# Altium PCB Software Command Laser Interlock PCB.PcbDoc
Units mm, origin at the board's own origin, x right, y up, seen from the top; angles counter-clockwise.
Board outline 50 x 70 mm, 2 copper layers (Top Layer, Bottom Layer); 14 components, 12 nets, 69 pads, 8 vias.
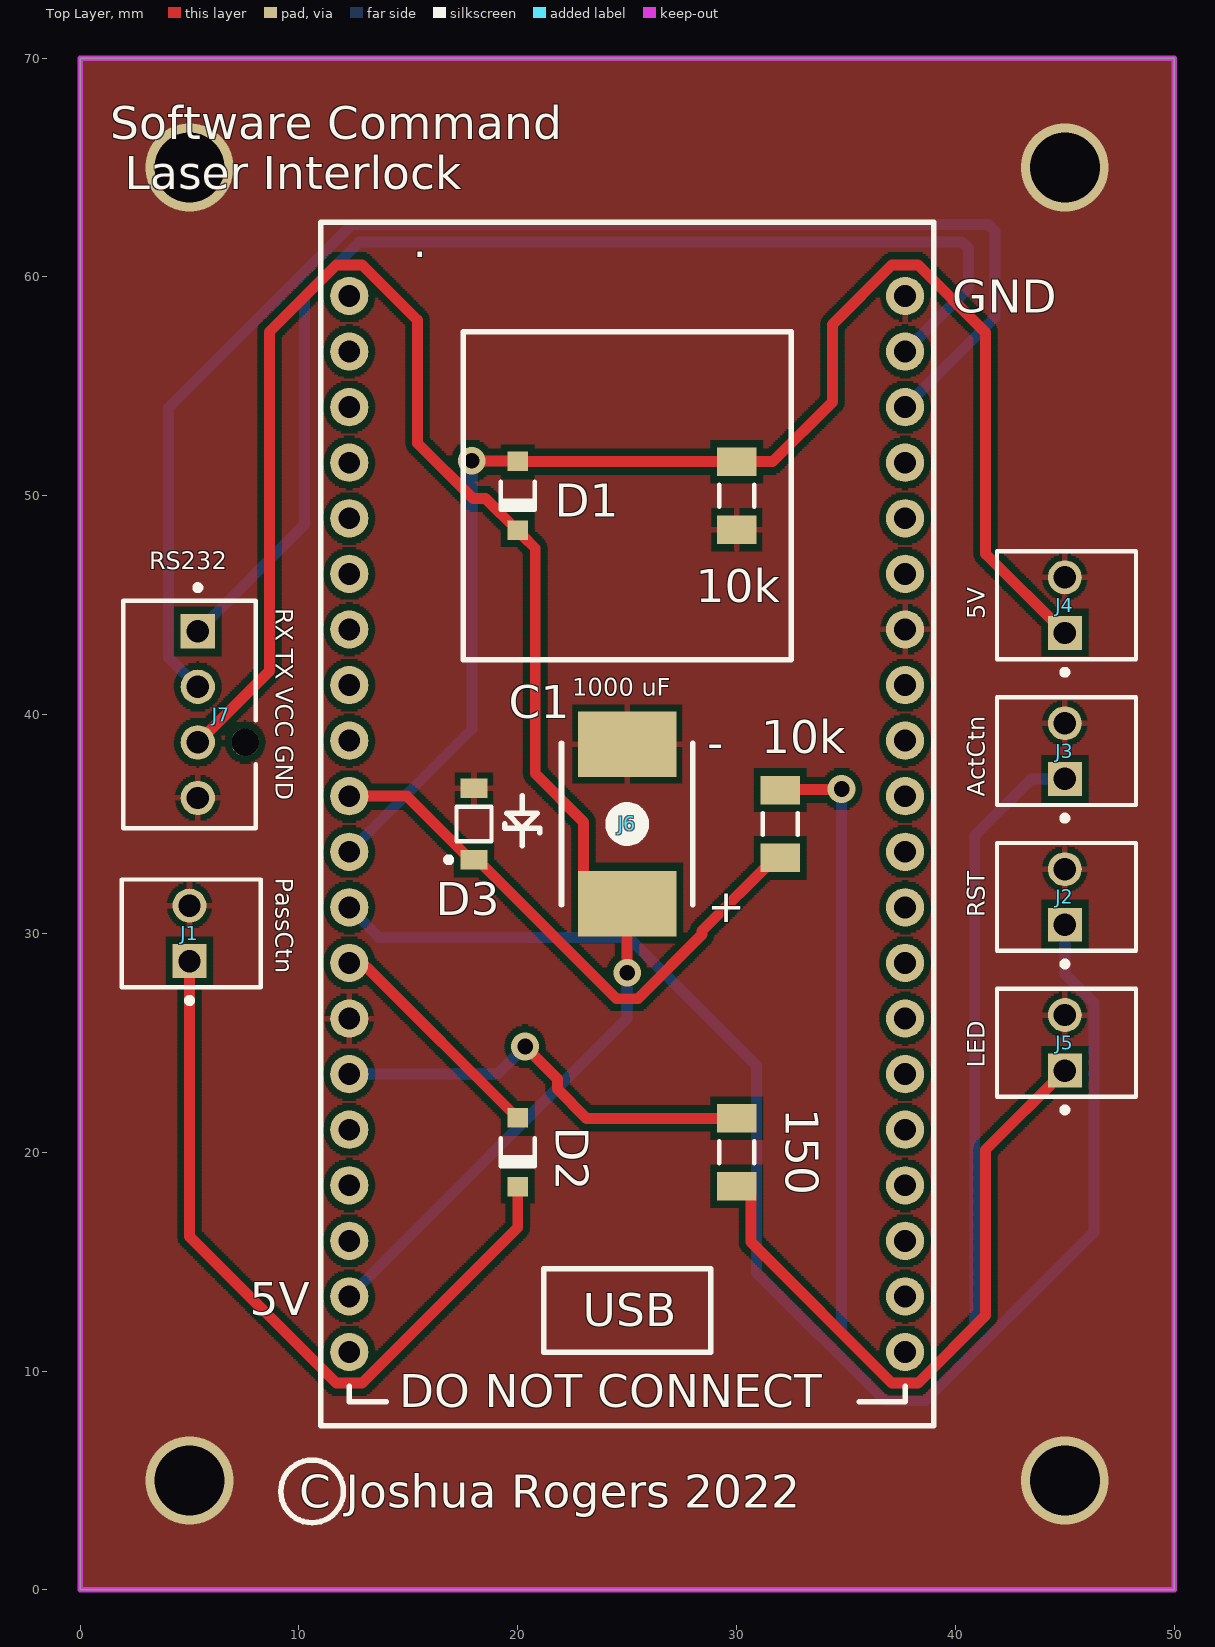
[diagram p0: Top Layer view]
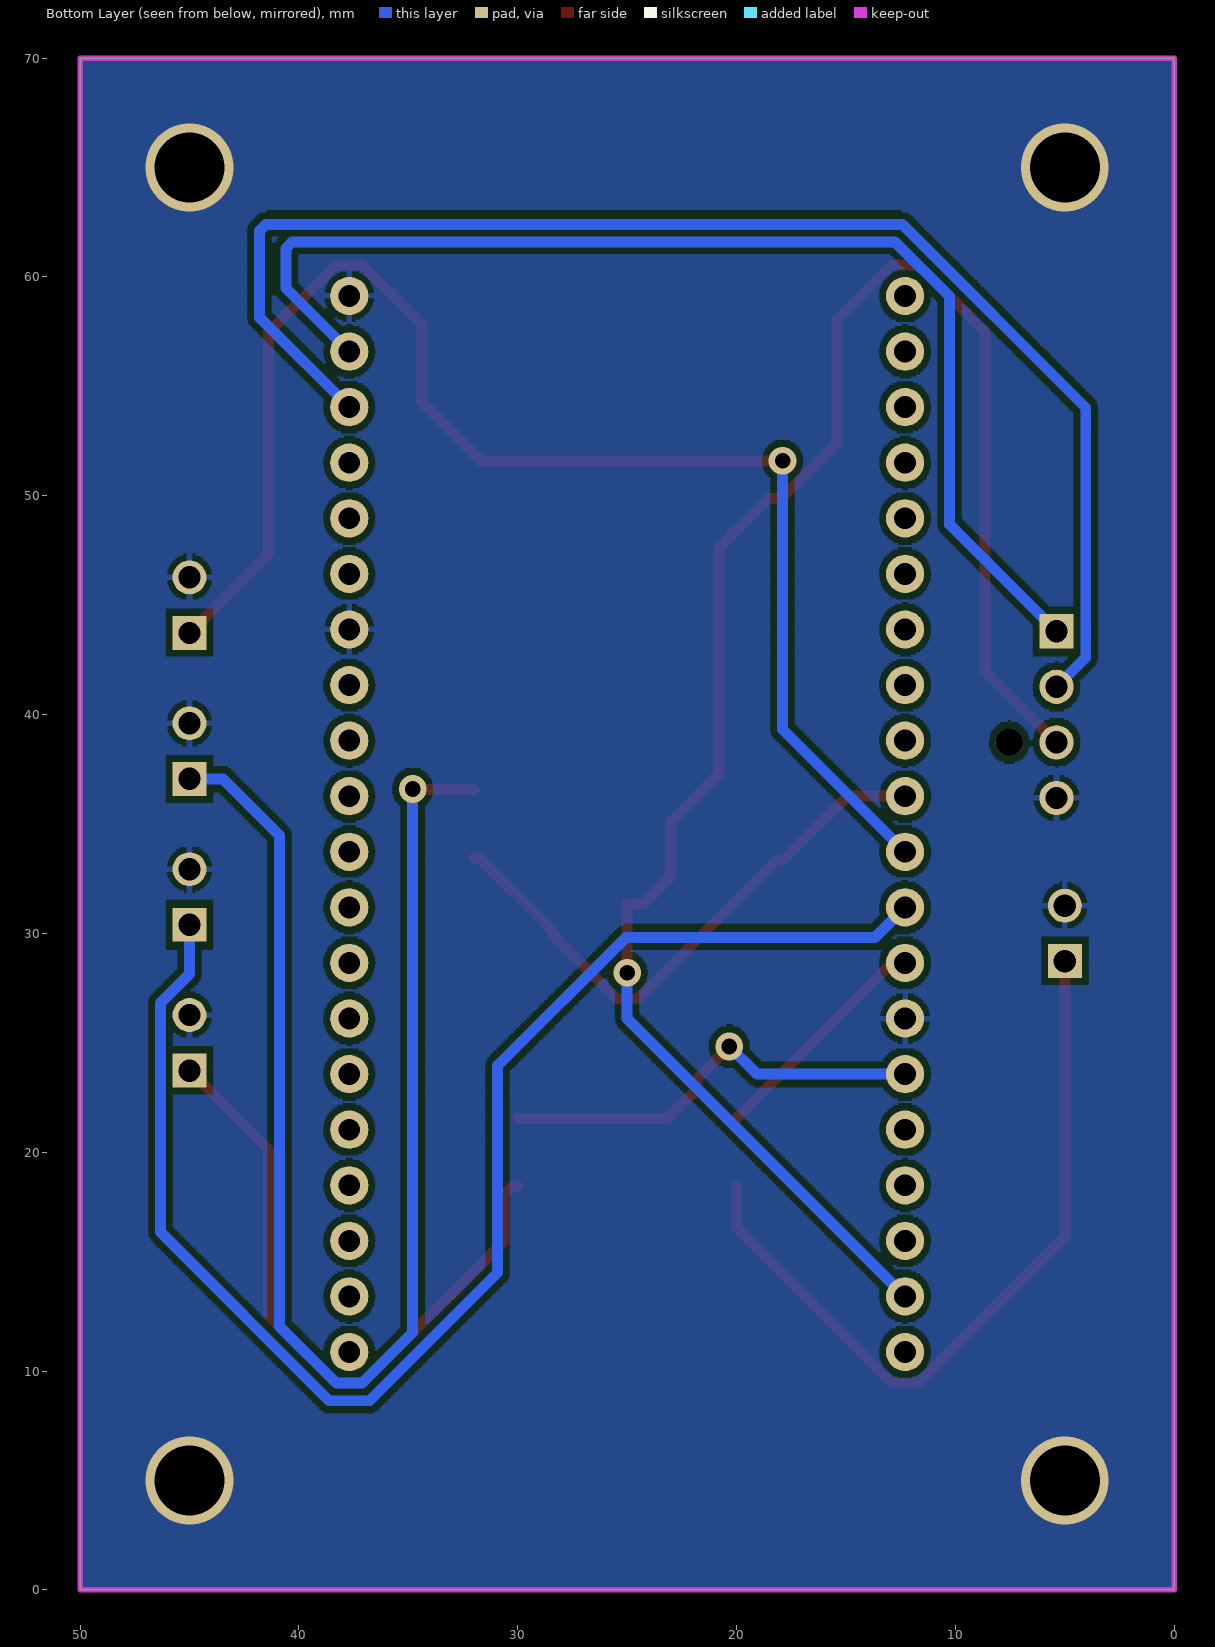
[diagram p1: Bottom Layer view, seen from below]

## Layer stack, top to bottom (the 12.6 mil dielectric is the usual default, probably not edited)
Top Solder: solder mask 0.0102, Solder Resist, Dk 3.5
Top Layer: signal copper 0.0356
Dielectric 1: dielectric 0.32, FR-4, Dk 4.8
Bottom Layer: signal copper 0.0356
Bottom Solder: solder mask 0.0102, Solder Resist, Dk 3.5

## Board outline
0,0 0,70 50,70 50,0

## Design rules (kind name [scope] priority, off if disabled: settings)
Clearance [All] p1: gap=0.3 ignorepadtopadclearanceinfootprint=FALSE
DiffPairsRouting [All] p1: maxlimit=2 minlimit=0.3 mostfreqgap=0.5 toplayer_minwidth=0.3 toplayer_maxwidth=2 toplayer_prefwidth=0.5 bottomlayer_minwidth=0.3 bottomlayer_maxwidth=2 bottomlayer_prefwidth=0.5 maxuncoupledlength=12.7
HoleSize [All] p1: absolutevalues=TRUE maxlimit=10 minlimit=0.3 maxpercent=80.000 minpercent=20.000
HoleToHoleClearance [All] p1: gap=0.6 allowstackedmicrovias=TRUE
MinimumSolderMaskSliver [All] p1: minsoldermaskwidth=0.3
PolygonConnect [All] p1: connectstyle=Relief reliefconductorwidth=0.254 reliefentries=4 polygonreliefangle="90 Angle" airgapwidth=0.254
RoutingVias [All] p1: holewidth=0.711 width=1.27 viastyle="Through Hole" minholewidth=0.711 minwidth=1.27 maxholewidth=0.711 maxwidth=1.27
SilkToSilkClearance [All] p1: silktosilkclearance=0.3
SolderMaskExpansion [All] p1: expansion=0.102 istentingtop=FALSE
Width [All] p1: maxlimit=2 minlimit=0.3 preferedwidth=0.5
25 further rules are at their usual default settings.

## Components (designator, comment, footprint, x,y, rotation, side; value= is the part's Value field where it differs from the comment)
10k "CRCW120610K0JNEA" RESC3216X60X45ML10T20 32,35 r270 top (schematic designator R3)
10k "CRCW120610K0JNEA" RESC3216X60X45ML10T20 30,50 r90 top (schematic designator R1)
150 "CRCW1206150RFKEA" RESC3216X60X45ML10T20 30,20 r90 top (schematic designator R2)
C1 "1000 uF SMD cap" "1000 uF SMD Cap" 25,35 r0 top
D1 "1N4148W-7-F" DIOD-SOD123-2_V 20,50 r270 top
D2 "1N4148W-7-F" DIOD-SOD123-2_V 20,20 r270 top
D3 "MMSZ4688T1G" ONSC-SOD-123-2-425-04_V 18,35 r90 top
J1 "22-23-2021" MOLX-22-23-2021_V 5,30 r90 top
J2 "22-23-2021" MOLX-22-23-2021_V 45,31.667 r90 top
J3 "22-23-2021" MOLX-22-23-2021_V 45,38.333 r90 top
J4 "22-23-2021" MOLX-22-23-2021_V 45,45 r90 top
J5 "22-23-2021" MOLX-22-23-2021_V 45,25 r90 top
J6 "ESP32" "ESP32 FOOTPRINT" 25,35 r0 top
J7 "47053-1000" FP-47053-1000-MFG 5,40 r90 top

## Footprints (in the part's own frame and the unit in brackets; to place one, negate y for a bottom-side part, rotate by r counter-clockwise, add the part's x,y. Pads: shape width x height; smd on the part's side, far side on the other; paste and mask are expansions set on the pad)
"1000 uF SMD Cap" [mm]
  rect 4.5x3 smd: 1(0,3.65) 2(0,-3.65)
  silkscreen extent -3,-3.7 3,3.7
DIOD-SOD123-2_V [mm] "SOD123, 2-Leads, Body 2.7x1.55mm, Height 1.45mm"
  rect 0.9x0.95 smd: 1(-1.575,0) 2(1.575,0)
  silkscreen extent -0.64,-0.82 0.64,0.77, body extent -1.35,-0.77 1.35,0.77, height 1.45
"ESP32 FOOTPRINT" [mm]
  round 1.75 hole 1: 1(-12.7,24.13) 2(-12.7,21.59) 3(-12.7,19.05) 4(-12.7,16.51) 5(-12.7,13.97) 6(-12.7,11.43) 7(-12.7,8.89) 8(-12.7,6.35) 9(-12.7,3.81) 10(-12.7,1.27) 11(-12.7,-1.27) 12(-12.7,-3.81) 13(-12.7,-6.35) 14(-12.7,-8.89) 15(-12.7,-11.43) 16(-12.7,-13.97) 17(-12.7,-16.51) 18(-12.7,-19.05) 19(-12.7,-21.59) 20(-12.7,-24.13) 21(12.7,24.13) 22(12.7,21.59) 23(12.7,19.05) 24(12.7,16.51) 25(12.7,13.97) 26(12.7,11.43) 27(12.7,8.89) 28(12.7,6.35) 29(12.7,3.81) 30(12.7,1.27) 31(12.7,-1.27) 32(12.7,-3.81) 33(12.7,-6.35) 34(12.7,-8.89) 35(12.7,-11.43) 36(12.7,-13.97) 37(12.7,-16.51) 38(12.7,-19.05) 39(12.7,-21.59) 40(12.7,-24.13)
  silkscreen extent -14,-27.5 14,27.5
FP-47053-1000-MFG [mm]
  rect 1.57x1.57 hole 1.02 paste-1000 mask+0: 1(3.81,-0.38)
  round 1.57 hole 1.02 paste-1000 mask+0: 2(1.27,-0.38) 3(-1.27,-0.38) 4(-3.81,-0.38)
  round 1.25 hole 1.25 unplated paste-1000 mask+0: ""(-1.27,-2.54)
  silkscreen extent -5.2,-3.02 5.92,3.02, body extent -5.3,-3.26 5.3,3.12, height 0.25
MOLX-22-23-2021_V [mm] "THD, 2-Leads, Body 6.35x4.93mm, Pitch 2.54mm"
  rect 1.55x1.55 hole 1.02: 1(-1.27,0)
  round 1.55 hole 1.02: 2(1.27,0)
  silkscreen extent -3.19,-3.25 2.46,3.1, body extent -2.46,-3.25 2.46,3.1, height 10.66
ONSC-SOD-123-2-425-04_V [mm] "SOD, 2-Leads, Body 2.69x1.6mm"
  rect 0.91x1.22 smd: 1(-1.635,0) 2(1.635,0)
  silkscreen extent -1.76,-0.8 0.78,1.28, body extent -1.35,-0.8 1.35,0.8, height 1.35
RESC3216X60X45ML10T20 [mm] "Chip Resistor, 2-Leads, Body 3.20x1.60mm, IPC Low Density"
  rect 1.3x1.8 smd: 1(-1.55,0) 2(1.55,0)
  silkscreen extent -0.5,-0.8 0.5,0.8, body extent -1.65,-0.85 1.65,0.85, height 0.6

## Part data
10k 10k: library part CMP-2003-04808-1, Manufacturer="Vishay Dale"
150: library part CMP-2003-01812-1, Manufacturer="Vishay Dale"
C1: "https://uk.farnell.com/kemet/t523h108m010ape070/cap-1000-f-10v-20/dp/2913804"
D1 D2: library part CMP-2000-04932-2, "Fast Switching Diode, 100 V, 0.15 A, -65 to 150 degC, 2-Pin?SOD123, RoHS, Tape and Reel", If - Forward Current=0.15A, Ir - Reverse Current=1uA, Manufacturer=DiodesIncorporated, Max Surge Current=2A, Maximum Operating Temperature=+150C, Minimum Operating Temperature=-65C, Operating Temperature Range=-65Cto+150C, Package / Case=SOD-123, Package Reference=SOD123-2, Peak Reverse Voltage=100V, Vf - Forward Voltage=1.25V
D3: library part CMP-1060-00561-1, "Zener Voltage Regulator, 500 mW, 2-Pin SOD-123, Pb-Free, Tape and Reel", Manufacturer="On Semiconductor"
J1 J2 J3 J4 J5: library part CMP-1704-00001-3, "Male Header, Pitch 2.54 mm, 1 x 2 Position, Height 10.67 mm, Tail Length 3.56 mm, 0 to 75 degC, RoHS, Bulk", Max Operating Temperature="75 degC", Min Operating Temperature="0 degC", Package Quantity=3000
J6: "2 x 1 row x 20 position header sockets to house the ESP32 DEV board"
J7: library part CMP-04776-000290-1, "CONN HEADER VERT 4POS 2.54MM", Current Rating=4A, Housing Color=Beige, Max Operating Temperature=75°C, Min Operating Temperature=0°C, Package Quantity=12000, Voltage Rating=250V

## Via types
v1: diameter 1.27, hole 0.711, Top Layer to Bottom Layer, 4 vias
v2: diameter 4, hole 3.2, Top Layer to Bottom Layer, 4 vias

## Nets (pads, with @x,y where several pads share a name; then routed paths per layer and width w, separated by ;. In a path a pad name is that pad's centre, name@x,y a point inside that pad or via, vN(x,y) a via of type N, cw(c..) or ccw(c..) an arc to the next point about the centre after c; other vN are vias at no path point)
5VPSU: 10k.2@30,51.55 D1.1 J4.1 J6.11 | length 66
  Top Layer w0.5: v1(17.9,51.6) 17.913,51.587 19.988,51.587 D1.1 20.013,51.562 31.65,51.562 34.38,54.292 34.38,57.825 37.11,60.555 38.29,60.555 41.383,57.463 41.383,47.347 J4.1
  Bottom Layer w0.5: J6.11 17.9,39.33 v1(17.9,51.6)
ActiveCurtain: 10k.1@32,36.55 J3.1 | length 63.4
  Top Layer w0.5: 10k.1@32,36.55 32.025,36.575 34.775,36.575 v1(34.8,36.6)
  Bottom Layer w0.5: v1(34.8,36.6) 34.8,11.755 37.11,9.445 38.29,9.445 40.883,12.037 40.883,34.471 43.475,37.063 J3.1
ActiveCurtainPin: 10k.2@32,33.45 D3.1 J6.10 | length 26.3
  Top Layer w0.5: J6.10 14.94,36.27 17.845,33.365 D3.1 18.155,33.365 24.505,27.015 25.491,27.015 28.42,29.945 28.42,30.12 31.75,33.45 10k.2@32,33.45
GND: 10k.1@30,48.45 C1.1 D3.2 J1.2 J2.2 J3.2 J4.2 J5.2 J6.14 J6.21 J6.27 J7.4
  other v2: 5,5 45,5 5,65 45,65
LED: 150.1 J5.1 | length 30.3
  Top Layer w0.5: 150.1 30.25,18.45 30.65,18.05 30.65,15.905 37.11,9.445 38.29,9.445 41.383,12.537 41.383,20.113 J5.1
LEDPin: 150.2 J6.15 | length 19.9
  Top Layer w0.5: v1(20.333,24.833) 21.815,23.351 21.815,22.885 23.15,21.55 150.2
  Bottom Layer w0.5: J6.15 19.07,23.57 v1(20.333,24.833)
PassiveCurtain: D2.2 J1.1 | length 35.2
  Top Layer w0.5: J1.1 5,16.155 11.71,9.445 12.89,9.445 20,16.555 D2.2
PassiveCurtainPin: D2.1 J6.13 | length 10.6
  Top Layer w0.5: J6.13 12.539,28.411 13.139,28.411 19.975,21.575 D2.1
ResetButton: J2.1 J6.12 | length 66.7
  Bottom Layer w0.5: J6.12 13.669,29.821 25.055,29.821 30.917,23.959 30.917,14.507 36.778,8.645 38.622,8.645 46.325,16.348 46.325,26.819 45,28.144 J2.1
RX: J6.22 J7.1 | length 54.7
  Bottom Layer w0.5: J7.1 10.261,48.691 10.261,59.106 12.755,61.6 40.307,61.6 40.6,61.307 40.6,59.49 J6.22
TX: J6.23 J7.2 | length 64.4
  Bottom Layer w0.5: J7.2 4.045,42.605 4.045,54.022 12.423,62.4 41.507,62.4 41.8,62.107 41.8,58.15 J6.23
VCC: C1.2 D1.2 J6.19 J7.3 | length 83.9
  Top Layer w0.5: J7.3 8.647,41.997 8.647,57.492 11.71,60.555 12.89,60.555 15.424,58.022 15.424,52.4 17.957,49.867 18.533,49.867 19.975,48.425 D1.2 20.025,48.425 20.225,48.225 20.225,48.175 20.8,47.6 20.8,37.3 23,35.1 23,32.6 24.25,31.35 C1.2 v1(25,28.2)
  Bottom Layer w0.5: J6.19 25,26.11 v1(25,28.2)
pads on no net: J6.1 J6.2 J6.3 J6.4 J6.5 J6.6 J6.7 J6.8 J6.9 J6.16 J6.17 J6.18 J6.20 J6.24 J6.25 J6.26 J6.28 J6.29 J6.30 J6.31 J6.32 J6.33 J6.34 J6.35 J6.36 J6.37 J6.38 J6.39 J6.40 J7.

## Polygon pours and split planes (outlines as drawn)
GND on Bottom Layer "GND_L02_P001" (hatched Horizontal grid 0.1 track 0.1, pour order 1): 0,0 50,0 50,70 0,70
GND on Top Layer "GND_L01_P000" (hatched Horizontal grid 0.1 track 0.1, pour order 0): 0,0 50,0 50,70 0,70

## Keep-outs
Keep-Out Layer:
  the board outline again, w0.254

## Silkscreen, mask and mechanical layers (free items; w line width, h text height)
Top Overlay:
  circle w0.254: c10.6,4.5 r1.432
  lines w0.254: 19.4,35 19.4,34.8 21,34.8 21,34.6 ; 20.2,34 20.2,34.8 ; 20.2,35.6 20.2,36.3 ; 20.2,34.8 20.9,35.5 19.5,35.5 20.2,34.8
  text "Software Command /  Laser Interlock" at 1.386,64 h1.52
  text "RS232" at 3.15,46.65 h0.8
  text "RX TX VCC GND" at 8.95,44.85 h0.8 r270
  text "5V" at 41.35,44.35 h0.8 r90
  text "1000 uF" at 22.501,40.85 h0.8
  text "ActCtn" at 41.35,36.25 h0.8 r90
  text "PassCtn" at 8.95,32.55 h0.8 r270
  text "RST" at 41.35,30.75 h0.8 r90
  text "LED" at 41.35,23.85 h0.8 r90
  text "C Joshua Rogers 2022" at 10.019,3.762 h1.52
